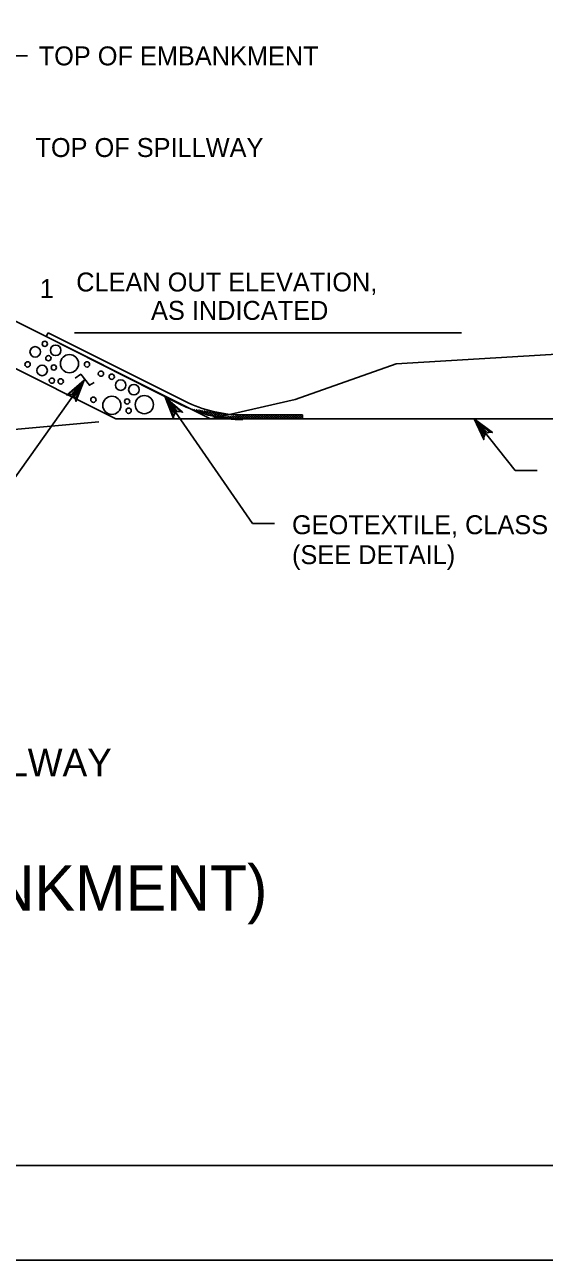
# Model space of a CAD drawing. Extents: x 636462 to 639890, y 299944 to 300538.
# Drawn here: x 636766.5 to 636848.8, y 299944.4 to 300140 of the extents above; entities that cross this region are included whole.
import ezdxf

# ---------------------------------------------------------------- set-up
doc = ezdxf.new("R2010")
doc.units = 0
for name, color, linetype in [('1', 7, 'Continuous'), ('Default', 7, 'Continuous'), ('PLT-BNDY', 7, 'Continuous')]:
    doc.layers.add(name, color=color, linetype=linetype)

msp = doc.modelspace()

# ---------------------------------------------------------------- linework, layer by layer
at = {"layer": '1'}
for points in [[(637287.91, 299959.45), (637287.91, 300523.45), (636501.91, 300523.45), (636501.91, 299959.45), (637287.91, 299959.45), (637287.91, 299985.81), (637087.91, 299985.81), (637087.91, 300050.49), (637287.91, 300050.49), (637287.91, 300079.45), (637087.91, 300079.45), (637087.91, 299959.45), (637166.72, 299959.45), (637166.72, 299985.81), (637166.72, 299959.45), (637243.72, 299959.45), (637243.72, 299985.81), (637243.72, 299973.49), (637287.91, 299973.49)], [(636774.51, 300084.06), (636775.41, 300084.66), (636776.79, 300082.92), (636777.56, 300083.34)]]:
    msp.add_lwpolyline(points, dxfattribs=at)
at = {"layer": 'Default'}
for p, q in [((636767.01, 300135.04), (636763.51, 300135.04)), ((636718.64, 300116.25), (636795.95, 300077.59)), ((636725.28, 300105.44), (636780.98, 300077.59)), ((636770.25, 300091.22), (636769.95, 300090.61)), ((636770.25, 300091.22), (636791.89, 300080.41)), ((636774.45, 300091.22), (636835.73, 300091.22)), ((636769.95, 300090.61), (636791.54, 300079.7)), ((636775.94, 300083.72), (636756.96, 300056.99)), ((636788.81, 300081.03), (636802.6, 300061.06)), ((636780.98, 300077.59), (636864.17, 300077.59)), ((636792.87, 300079.19), (636792.84, 300079.16)), ((636792.93, 300079.18), (636793.02, 300079.08)), ((636793.18, 300079.14), (636793.09, 300079.05)), ((636793.33, 300079.12), (636793.61, 300078.85)), ((636793.49, 300079.1), (636793.34, 300078.95)), ((636793.8, 300079.06), (636793.6, 300078.86)), ((636793.74, 300079.07), (636794.16, 300078.65)), ((636794.11, 300079.02), (636793.85, 300078.76)), ((636794.42, 300078.97), (636794.12, 300078.67)), ((636794.15, 300079.01), (636794.68, 300078.48)), ((636794.73, 300078.93), (636794.38, 300078.58)), ((636794.56, 300078.95), (636795.19, 300078.33)), ((636795.04, 300078.89), (636794.65, 300078.49)), ((636795.35, 300078.85), (636794.92, 300078.41)), ((636794.97, 300078.9), (636795.68, 300078.19)), ((636795.66, 300078.8), (636795.19, 300078.33)), ((636795.38, 300078.84), (636796.15, 300078.08)), ((636795.97, 300078.76), (636795.46, 300078.25)), ((636796.29, 300078.72), (636795.74, 300078.18)), ((636795.79, 300078.79), (636796.61, 300077.97)), ((636796.6, 300078.68), (636796.03, 300078.11)), ((636796.2, 300078.73), (636797.05, 300077.88)), ((636796.91, 300078.63), (636796.31, 300078.04)), ((636797.22, 300078.59), (636796.6, 300077.97)), ((636796.61, 300078.67), (636797.37, 300077.92)), ((636797.53, 300078.55), (636796.89, 300077.91)), ((636797.02, 300078.62), (636797.65, 300077.99)), ((636797.84, 300078.51), (636797.22, 300077.89)), ((636797.28, 300077.88), (636797.25, 300077.84)), ((636797.35, 300077.89), (636797.42, 300077.81)), ((636797.43, 300078.56), (636797.94, 300078.05)), ((636797.67, 300077.92), (636797.55, 300077.79)), ((636797.67, 300077.92), (636797.84, 300077.74)), ((636798.15, 300078.46), (636797.68, 300077.99)), ((636797.84, 300078.51), (636798.23, 300078.12)), ((636798.06, 300077.95), (636797.85, 300077.74)), ((636797.99, 300077.95), (636798.25, 300077.68)), ((636798.46, 300078.42), (636798.14, 300078.1)), ((636798.45, 300077.99), (636798.16, 300077.7)), ((636798.25, 300078.45), (636798.51, 300078.18)), ((636798.32, 300077.98), (636798.66, 300077.63)), ((636798.84, 300078.02), (636798.47, 300077.66)), ((636798.77, 300078.38), (636798.6, 300078.2)), ((636798.64, 300078.01), (636799.05, 300077.59)), ((636798.66, 300078.39), (636798.8, 300078.25)), ((636799.23, 300078.06), (636798.79, 300077.62)), ((636798.96, 300078.04), (636799.41, 300077.59)), ((636799.08, 300078.34), (636799.06, 300078.31)), ((636799.07, 300078.34), (636799.09, 300078.32)), ((636799.62, 300078.1), (636799.12, 300077.59)), ((636799.29, 300078.07), (636799.76, 300077.59)), ((636800.01, 300078.13), (636799.47, 300077.59)), ((636799.61, 300078.1), (636800.11, 300077.59)), ((636800.4, 300078.17), (636799.82, 300077.59)), ((636799.93, 300078.13), (636800.47, 300077.59)), ((636800.79, 300078.21), (636800.18, 300077.59)), ((636800.26, 300078.16), (636800.82, 300077.59)), ((636801.17, 300078.23), (636800.53, 300077.59)), ((636800.58, 300078.19), (636801.17, 300077.59)), ((636801.53, 300078.23), (636800.88, 300077.59)), ((636800.9, 300078.22), (636801.53, 300077.59)), ((636801.1, 300078.23), (636810.54, 300078.23)), ((636801.1, 300077.59), (636810.54, 300077.59)), ((636801.24, 300078.23), (636801.88, 300077.59)), ((636801.88, 300078.23), (636801.24, 300077.59)), ((636801.59, 300078.23), (636802.23, 300077.59)), ((636802.23, 300078.23), (636801.59, 300077.59)), ((636801.94, 300078.23), (636802.59, 300077.59)), ((636802.59, 300078.23), (636801.94, 300077.59)), ((636802.3, 300078.23), (636802.94, 300077.59)), ((636802.94, 300078.23), (636802.3, 300077.59)), ((636802.65, 300078.23), (636803.29, 300077.59)), ((636803.29, 300078.23), (636802.65, 300077.59)), ((636803, 300078.23), (636803.65, 300077.59)), ((636803.65, 300078.23), (636803, 300077.59)), ((636803.36, 300078.23), (636804, 300077.59)), ((636804, 300078.23), (636803.36, 300077.59)), ((636803.71, 300078.23), (636804.35, 300077.59)), ((636804.35, 300078.23), (636803.71, 300077.59)), ((636804.06, 300078.23), (636804.71, 300077.59)), ((636804.7, 300078.23), (636804.06, 300077.59)), ((636804.42, 300078.23), (636805.06, 300077.59)), ((636805.06, 300078.23), (636804.42, 300077.59)), ((636804.77, 300078.23), (636805.41, 300077.59)), ((636805.41, 300078.23), (636804.77, 300077.59)), ((636805.12, 300078.23), (636805.77, 300077.59)), ((636805.76, 300078.23), (636805.12, 300077.59)), ((636805.48, 300078.23), (636806.12, 300077.59)), ((636806.12, 300078.23), (636805.48, 300077.59)), ((636805.83, 300078.23), (636806.47, 300077.59)), ((636806.47, 300078.23), (636805.83, 300077.59)), ((636806.18, 300078.23), (636806.83, 300077.59)), ((636806.82, 300078.23), (636806.18, 300077.59)), ((636806.54, 300078.23), (636807.18, 300077.59)), ((636807.18, 300078.23), (636806.54, 300077.59)), ((636806.89, 300078.23), (636807.53, 300077.59)), ((636807.53, 300078.23), (636806.89, 300077.59)), ((636807.24, 300078.23), (636807.89, 300077.59)), ((636807.88, 300078.23), (636807.24, 300077.59)), ((636807.6, 300078.23), (636808.24, 300077.59)), ((636808.24, 300078.23), (636807.6, 300077.59)), ((636807.95, 300078.23), (636808.59, 300077.59)), ((636808.59, 300078.23), (636807.95, 300077.59)), ((636808.3, 300078.23), (636808.95, 300077.59)), ((636808.94, 300078.23), (636808.3, 300077.59)), ((636808.66, 300078.23), (636809.3, 300077.59)), ((636809.3, 300078.23), (636808.66, 300077.59)), ((636809.01, 300078.23), (636809.65, 300077.59)), ((636809.65, 300078.23), (636809.01, 300077.59)), ((636809.36, 300078.23), (636810.01, 300077.59)), ((636810, 300078.23), (636809.36, 300077.59)), ((636809.72, 300078.23), (636810.36, 300077.59)), ((636810.36, 300078.23), (636809.72, 300077.59)), ((636810.07, 300078.23), (636810.54, 300077.76)), ((636810.54, 300078.07), (636810.07, 300077.59)), ((636810.42, 300078.23), (636810.54, 300078.11)), ((636810.54, 300077.71), (636810.42, 300077.59)), ((636810.54, 300078.23), (636810.54, 300077.59)), ((636837.7, 300077.59), (636844.2, 300069.42)), ((636847.7, 300069.42), (636844.2, 300069.42)), ((636806.1, 300061.06), (636802.6, 300061.06))]:
    msp.add_line(p, q, dxfattribs=at)
for points in [[(636950.05, 300122.72), (636920.65, 300119.05), (636899.64, 300111.72), (636876.9, 300095.25), (636854.3, 300088.04), (636825.36, 300086.31), (636809.35, 300080.69), (636795.95, 300077.59), (636795.95, 300077.59)], [(636773.55, 300081.45), (636773.21, 300081.36), (636775.94, 300083.72), (636773.55, 300081.45), (636773.96, 300081.4), (636775.94, 300083.72), (636774.39, 300081.1), (636774.59, 300080.73), (636775.94, 300083.72), (636774.64, 300080.35), (636774.59, 300080.73)], [(636790.13, 300078.01), (636790.1, 300077.66), (636788.81, 300081.03), (636790.13, 300078.01), (636790.32, 300078.39), (636788.81, 300081.03), (636790.75, 300078.69), (636791.16, 300078.75), (636788.81, 300081.03), (636791.53, 300078.66), (636791.16, 300078.75)], [(636610.06, 300077.59), (636634.29, 300073.12), (636661.65, 300076.54), (636689.51, 300078.01), (636709.06, 300074.1), (636733.97, 300073.12), (636778.26, 300077.15)], [(636839.23, 300074.68), (636839.23, 300074.33), (636837.7, 300077.59), (636839.23, 300074.68), (636839.4, 300075.06), (636837.7, 300077.59), (636839.8, 300075.4), (636840.21, 300075.49), (636837.7, 300077.59), (636840.59, 300075.43), (636840.21, 300075.49)]]:
    msp.add_lwpolyline(points, dxfattribs=at)
for centre, radius in [((636769.72, 300089.47), 0.417), ((636771.44, 300088.45), 0.835), ((636768.21, 300088.2), 0.835), ((636770.3, 300087.2), 0.417), ((636773.63, 300086.34), 1.44), ((636767, 300086.22), 0.417), ((636769.3, 300085.27), 0.835), ((636771.15, 300085.73), 0.417), ((636776.41, 300086.22), 0.417), ((636770.85, 300083.65), 0.417), ((636772.25, 300083.53), 0.417), ((636778.61, 300084.75), 0.417), ((636780.32, 300084.27), 0.417), ((636781.74, 300082.94), 0.835), ((636783.83, 300082.22), 0.835), ((636777.42, 300080.63), 0.417), ((636780.35, 300079.74), 1.44), ((636782.76, 300080.36), 0.417), ((636785.48, 300079.86), 1.44), ((636783, 300078.89), 0.417)]:
    msp.add_circle(centre, radius, dxfattribs=at)
for radius in [21.32, 20.58]:
    msp.add_arc((636801.1, 300098.81), radius, 243.4341, 270, dxfattribs=at)
at = {"layer": 'PLT-BNDY'}
msp.add_lwpolyline([(636461.91, 300538.45), (637302.91, 300538.45), (637302.91, 299944.45), (636461.91, 299944.45)], close=True, dxfattribs=at)

# ---------------------------------------------------------------- texts
at = {"layer": 'Default'}
for s, height, p in [('TOP OF EMBANKMENT', 2.998, (636768.76, 300133.54)), ('TOP OF SPILLWAY', 2.998, (636768.25, 300119.04)), ('1', 3, (636768.93, 300096.72)), ('CLEAN OUT ELEVATION,', 2.998, (636774.7, 300097.76)), ('AS INDICATED', 2.998, (636786.55, 300093.27)), ('GEOTEXTILE, CLASS 4, TYPE A', 2.998, (636808.87, 300059.35)), ('(SEE DETAIL)', 2.998, (636808.87, 300054.61)), ('SECTION VIEW THROUGH SPILLWAY', 4.3721, (636675.74, 300021.05)), ('SEDIMENT TRAP (EMBANKMENT)', 7.1953, (636649.95, 299999.78))]:
    msp.add_text(s, height=height, dxfattribs=at).set_placement(p)

doc.saveas('drawing.dxf')
